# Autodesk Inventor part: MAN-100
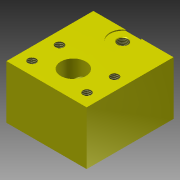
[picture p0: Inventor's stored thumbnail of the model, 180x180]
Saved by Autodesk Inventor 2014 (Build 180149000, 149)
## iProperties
Created: 2006-02
Part Number: MAN-100
Document SubType Name: Modeling
Designer: C Bull
Manufacturer: Standard
Standards Organization: Custom
Material: SAE 1020
Mass: 3910.59 g
Surface Area: 647.837 cm^2
Volume: 497.53 cm^3
Density: 7.86 g/cm^3
Appearance: Smooth - Yellow
RuleStatus: InUse
Author: C Bull
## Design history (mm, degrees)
sketch "Sketch2"
  geometry: L1 (38.1, -41.275)-(-38.1, -41.275); L2 (-38.1, -41.275)-(-38.1, 41.275); L3 (-38.1, 41.275)-(38.1, 41.275); L4 (38.1, 41.275)-(38.1, -41.275); L5 (-26.162, -28.956)-(26.162, -2.794); 7 further points
  constraints: 10 end point, 3 horizontal alignment, 3 midpoint, 3 vertical alignment, 2 parallel, 1 coincident, 1 horizontal, 1 perpendicular
  dimensions: "block_height" = 82.55 distance of L3.end L1.start; "block_width" = 76.2 distance of L1.start L1.end; "port_a_vert_offset" = 57.15 distance from line of point (0, -15.875) L3; "port_a_hor_offset" = 38.1 distance from line of point (0, -15.875) L4; "port_a_x_dist_between_screw" = 52.324 distance of L5.end point (-26.162, -2.794); "port_a_y_dist_between_screw" = 26.162 distance of L5.end point (26.162, -28.956)
extrude "Extrusion1" new body sketch "Sketch2" taper "d8" = 0 deg; distance "block_depth" = 50.8
hole "Port_A" sketch "Sketch2" diameter "port_a_port_dia" = 23.876; stored, may be unused: countersink angle "d13" = 90 deg, drill point angle "port_a_drill_tip_angle" = 118 deg; dims "d10" = 6, "d11" = 4, "d12" = 2, "port_a_d_d" = 25.4 (derived)
hole "Port_A_Threads" sketch "Sketch2" diameter "d16" = 7.7978; stored, may be unused: countersink angle "d20" = 90 deg, drill point angle "d22" = 118 deg; dims "d17" = 6, "d18" = 4, "d19" = 2, "d21" = 12.827 (derived)
sketch "Sketch3"
  geometry: L1 (38.1, -42.357)-(38.1, 40.193) reference; 1 further point
  dimensions: "SAE_Port" = 38.1 distance from line of point (0, 30.193) L1 (= port_a_hor_offset); "d24" = 10 vertical distance of point (0, 30.193) L1.end
feature "iFeature7:1" sketch "Sketch3"
sketch "Sketch4"
  geometry: L1 (76.2, -50.8)-(76.2, 0) reference; L2 (11.938, -38.481)-(64.262, -12.319); 5 further points
  constraints: 2 end point, 2 horizontal alignment, 2 vertical alignment, 1 coincident, 1 midpoint
  dimensions: "port_c_hor_offset" = 38.1 distance from line of point (38.1, -25.4) L1; "port_c_depth_from_front" = 25.4 vertical distance of point (38.1, -25.4) L1.start; "port_c_x_dist_between_screw" = 52.324 distance of point (64.262, -38.481) L2.start; "port_c_y_dist_between_screw" = 26.162 distance of L2.end point (64.262, -38.481)
hole "Port_C" sketch "Sketch4" diameter "port_c_port_dia" = 23.876; stored, may be unused: countersink angle "d33" = 90 deg, drill point angle "port_c_drill_tip_angle" = 118 deg; dims "d30" = 6, "d31" = 4, "d32" = 2, "port_c_vert_offset" = 57.15
hole "Port_C_Threads" sketch "Sketch4" diameter "d36" = 7.7978; stored, may be unused: countersink angle "d40" = 90 deg, drill point angle "d42" = 118 deg; dims "d37" = 6, "d38" = 4, "d39" = 2, "d41" = 12.827 (derived)
sketch "Sketch5"
  geometry: L1 (38.1, 41.275)-(38.1, -41.275) reference; L2 (38.1, -41.275)-(-38.1, -41.275) reference; L3 (26.162, 2.794)-(-26.162, 28.956); 4 further points
  constraints: 2 end point, 2 horizontal alignment, 2 vertical alignment, 1 coincident, 1 midpoint
  dimensions: "port_b_x_dist_between_screw" = 52.324 distance of L3.start point (-26.162, 2.794); "port_b_y_dist_between_screw" = 26.162 distance of point (26.162, 28.956) L3.start; "port_b_vert_offset" = 57.15 distance from line of point (0, 15.875) L2; "port_b_hor_offset" = 38.1 distance from line of L1 point (0, 15.875)
hole "Port_B" sketch "Sketch5" diameter "port_b_port_dia" = 23.876; stored, may be unused: countersink angle "d51" = 82 deg, drill point angle "d53" = 118 deg; dims "d48" = 12.7, "d49" = 9.525, "d50" = 6.35, "port_b_d_d" = 25.4 (= 0.5 x block_depth)
hole "Port_B_Threads" sketch "Sketch5" diameter "d54" = 7.7978; stored, may be unused: countersink angle "d58" = 82 deg, drill point angle "d60" = 118 deg; dims "d55" = 12.7, "d56" = 9.525, "d57" = 6.35, "d59" = 12.827 (derived)
body "Solid1"
other parameters: "tap_dim" = 7.9375 [user parameter], "weight" = 13.83457 [user parameter], "working_press" = 3445000 [user parameter], "AA_SAE_dim" = 23.876 [user parameter], "Port_A_Drill_Depth" = 12.827 [user parameter], "Port_B_Drill_Depth" = 12.827 [user parameter], "Port_C_Drill_Depth" = 12.827 [user parameter]
